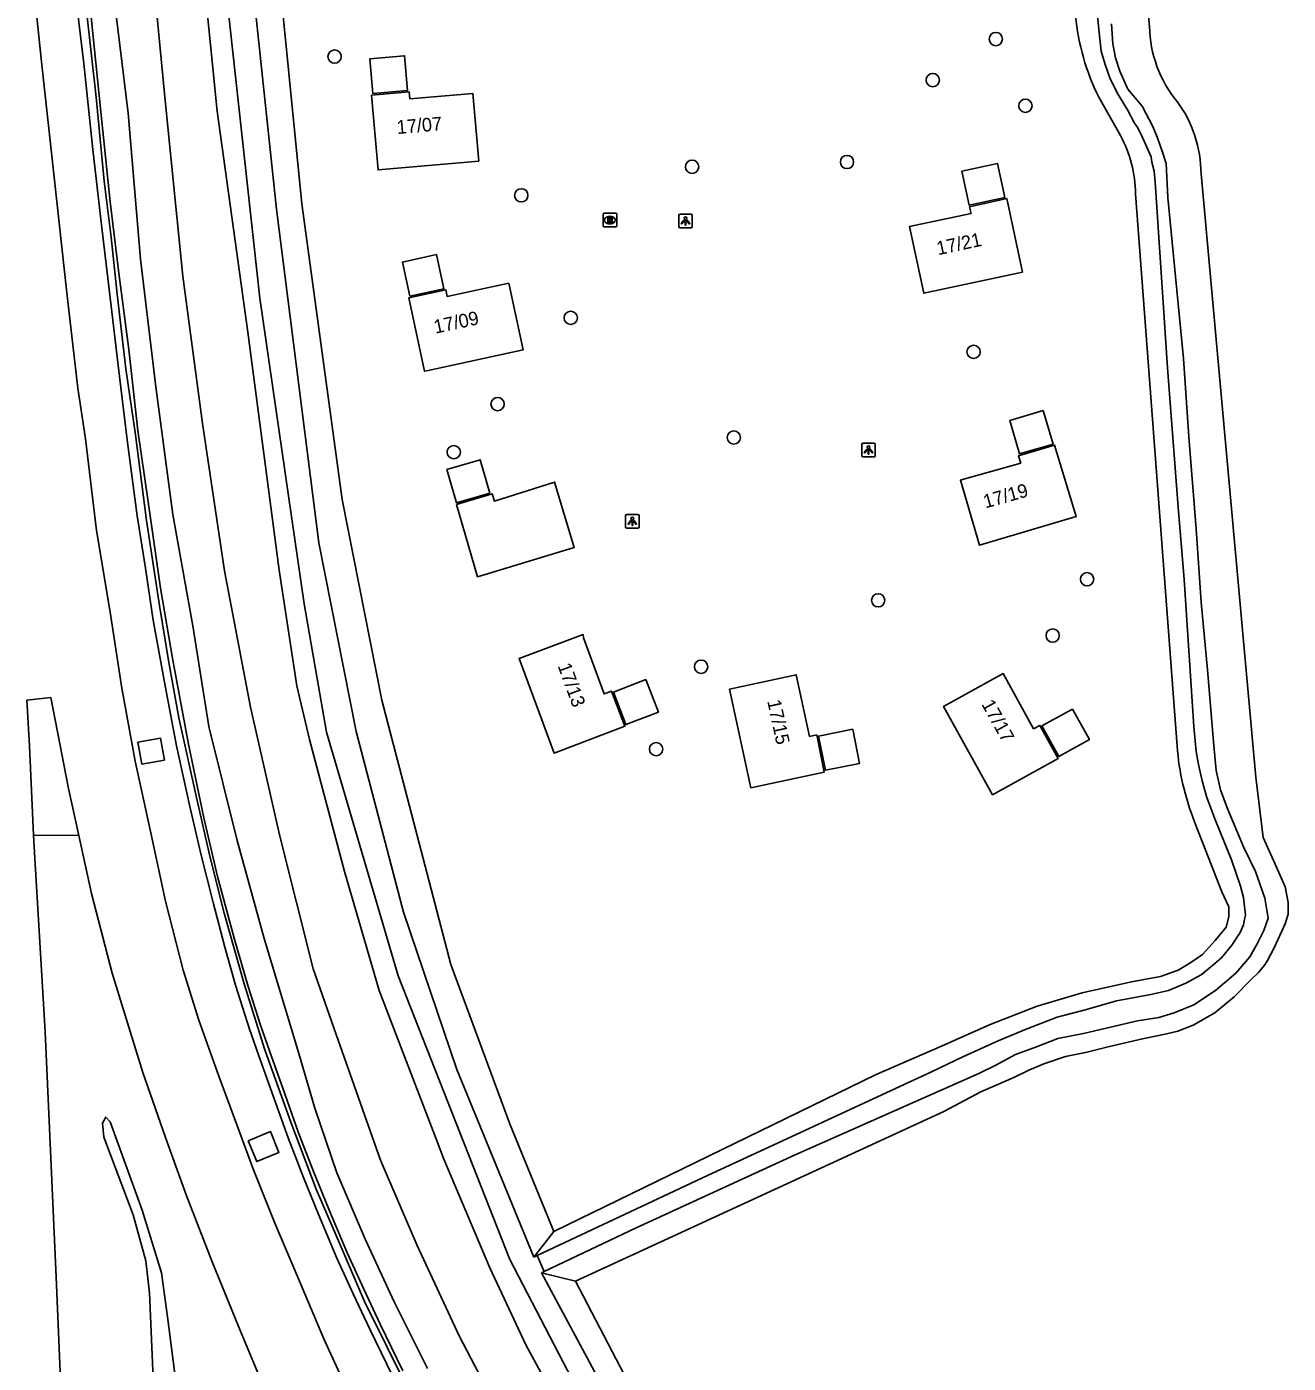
# Model space of a CAD drawing. Extents: x 157793 to 159380, y 380882 to 382313.
# Drawn here: x 157937.8 to 158030.6, y 381071.7 to 381170.1 of the extents above; entities that cross this region are included whole.
import ezdxf

# ---------------------------------------------------------------- set-up
doc = ezdxf.new("R2010")
doc.units = 0
for name, color, linetype in [('IMGEO_Berm_groen', 7, 'Continuous'), ('IMGEO_Berm_open', 7, 'Continuous'), ('IMGEO_Boom', 7, 'Continuous'), ('IMGEO_Geluidsscherm', 7, 'Continuous'), ('IMGEO_Grasland_overig', 7, 'Continuous'), ('IMGEO_Groenvoorziening', 7, 'Continuous'), ('IMGEO_Lichtpunt', 7, 'Continuous'), ('IMGEO_Muur', 7, 'Continuous'), ('IMGEO_Oever', 7, 'Continuous'), ('IMGEO_Pand', 7, 'Continuous'), ('IMGEO_Pand_nummerreeks', 7, 'Continuous'), ('IMGEO_Pand_vergunning_verleend', 7, 'Continuous'), ('IMGEO_Rijbaan_autoweg', 7, 'Continuous'), ('IMGEO_Rioolput', 7, 'Continuous'), ('IMGEO_Waterloop', 7, 'Continuous')]:
    doc.layers.add(name, color=color, linetype=linetype)

msp = doc.modelspace()

# ---------------------------------------------------------------- linework, layer by layer
at = {"layer": 'IMGEO_Berm_groen'}
for points in [[(157946.03, 381117.422), (157946.309, 381115.818), (157947.972, 381116.108), (157947.693, 381117.712), (157946.03, 381117.422)], [(157949.154, 381067.705), (157948.21, 381075.143), (157947.75, 381078.382), (157946.34, 381082.984), (157943.976, 381089.489), (157943.664, 381089.845), (157943.425, 381089.39), (157943.508, 381088.357), (157945.689, 381082.64), (157946.618, 381079.275), (157946.89, 381076.917), (157947.236, 381068.36)], [(157954.134, 381088.096), (157954.762, 381086.57), (157956.397, 381087.243), (157955.769, 381088.77), (157954.134, 381088.096)]]:
    msp.add_lwpolyline(points, dxfattribs=at)
at = {"layer": 'IMGEO_Berm_open'}
msp.add_lwpolyline([(157938.353, 381110.573), (157941.677, 381110.552)], dxfattribs=at)
at = {"layer": 'IMGEO_Boom'}
for centre in [(158009.132, 381169.157), (157960.493, 381167.864), (158004.492, 381166.14), (158011.308, 381164.25), (157998.185, 381160.109), (157986.791, 381159.761), (157974.228, 381157.657), (157977.862, 381148.644), (158007.497, 381146.143), (157972.484, 381142.3), (157989.858, 381139.842), (157969.256, 381138.76), (158015.843, 381129.408), (158000.478, 381127.86), (158013.314, 381125.266), (157987.454, 381122.977), (157984.142, 381116.908)]:
    msp.add_circle(centre, 0.489, dxfattribs=at)
at = {"layer": 'IMGEO_Geluidsscherm'}
msp.add_lwpolyline([(157942.251, 381171.224), (157942.964, 381164.872), (157943.555, 381158.711), (157944.056, 381154.583), (157944.505, 381150.378), (157945.148, 381144.887), (157945.845, 381140.036), (157946.668, 381133.736), (157947.611, 381127.489), (157948.287, 381123.427), (157949.046, 381119.227), (157950.385, 381113.14), (157951.307, 381109.043), (157952.366, 381104.849), (157953.831, 381099.642), (157955.371, 381094.796), (157957.264, 381089.477), (157959.132, 381084.541), (157960.921, 381080.39), (157962.699, 381076.283), (157964.365, 381072.915), (157966.426, 381068.742)], dxfattribs=at)
at = {"layer": 'IMGEO_Grasland_overig'}
for points in [[(157950.352, 381178.754), (157951.847, 381163.855), (157954.104, 381147.602), (157956.422, 381130.075), (157957.719, 381121.572), (157958.644, 381117.616), (157961.22, 381107.916), (157963.769, 381099.155), (157967.983, 381088.156), (157968.522, 381086.749), (157971.914, 381078.749), (157974.558, 381073.096), (157977.322, 381067.984), (157980.977, 381061.407), (157984.259, 381055.782), (157989.472, 381047.992), (157991.634, 381044.218), (157992.625, 381042.334), (157993.206, 381041.178), (157993.84, 381040.215), (157995.154, 381038.848), (157995.969, 381038.005)], [(157946.841, 381177.173), (157948.034, 381164.626), (157949.339, 381151.708), (157950.768, 381140.863), (157952.404, 381130.028), (157954.301, 381119.995), (157956.453, 381110.519), (157958.92, 381100.739), (157960.612, 381095.909), (157963.87, 381086.675), (157966.563, 381080.385), (157969.664, 381073.742), (157973.677, 381066.047)], [(157967.318, 381071.349), (157964.872, 381076.248), (157962.772, 381080.813), (157960.655, 381085.727), (157959.04, 381090.499), (157957.871, 381094.508), (157955.317, 381102.987), (157953.331, 381110.198), (157951.232, 381118.587), (157950.064, 381125.988), (157948.596, 381134.164), (157947.349, 381143.571), (157946.215, 381152.965), (157945.298, 381163.703), (157944.078, 381173.732)]]:
    msp.add_lwpolyline(points, dxfattribs=at)
at = {"layer": 'IMGEO_Groenvoorziening'}
for points in [[(157953.904, 381208.601), (157954.667, 381194.473), (157956.666, 381171.336), (157958.091, 381157.039), (157961.056, 381135.277), (157963.956, 381120.521), (157969.049, 381101.066), (157973.397, 381089.261), (157976.609, 381081.434)], [(158017.804, 381200.746), (158020.445, 381170.062)], [(158018.292, 381162.055), (158016.704, 381164.87)], [(158024.231, 381159.232), (158028.249, 381114.861), (158028.806, 381110.404), (158029.674, 381108.44), (158030.403, 381106.775), (158030.639, 381105.62), (158030.643, 381104.766), (158030.421, 381104.052), (158029.594, 381102.283), (158029.108, 381101.352), (158028.892, 381101.006), (158028.454, 381100.469), (158027.892, 381099.936), (158026.659, 381098.685), (158025.243, 381097.513), (158023.638, 381096.615), (158022.532, 381096.165), (158021.595, 381095.941), (158019.914, 381095.598), (158017.495, 381095.035), (158015.721, 381094.598), (158014.249, 381094.288), (158012.671, 381093.747), (158011.557, 381093.285), (158010.452, 381092.749), (158008.04, 381091.694), (158005.302, 381090.26), (157978.213, 381077.766)], [(158022.465, 381117.132), (158019.404, 381157.762)], [(157976.609, 381081.434), (158000.338, 381092.983), (158005.131, 381095.063), (158008.705, 381096.66), (158012.185, 381098.006), (158015.477, 381098.987), (158019.105, 381099.794), (158021.236, 381100.178), (158022.534, 381100.639), (158023.403, 381101.169), (158024.341, 381101.792), (158025.261, 381102.828), (158026.085, 381103.81), (158026.273, 381104.572), (158026.275, 381105.306), (158025.756, 381106.409), (158023.749, 381111.568)], [(157978.213, 381077.766), (157985.988, 381062.847), (157988.162, 381059.338)]]:
    msp.add_lwpolyline(points, dxfattribs=at)
for centre, radius, start, end in [((158032.528, 381172.642), 17.629, 185.77405, 206.15711), ((158029.237, 381170.181), 8.792, 180.7729, 219.65168), ((158015.08, 381159.168), 9.152, 0.39892, 36.17447), ((158010.58, 381157.767), 8.824, 359.96829, 29.0756), ((158041.64, 381118.627), 19.233, 184.45745, 201.53178)]:
    msp.add_arc(centre, radius, start, end, dxfattribs=at)
at = {"layer": 'IMGEO_Lichtpunt'}
for p, q in [((157985.809, 381156.175), (157985.809, 381155.368)), ((157985.809, 381156.175), (157985.809, 381155.368)), ((157986.711, 381156.27), (157985.903, 381156.27)), ((157986.711, 381156.27), (157985.903, 381156.27)), ((157986.805, 381155.368), (157986.805, 381156.175)), ((157986.805, 381155.368), (157986.805, 381156.175)), ((157985.903, 381155.274), (157986.711, 381155.274)), ((157985.903, 381155.274), (157986.711, 381155.274)), ((157999.271, 381139.327), (157999.271, 381138.52)), ((157999.271, 381139.327), (157999.271, 381138.52)), ((158000.173, 381139.422), (157999.365, 381139.422)), ((158000.173, 381139.422), (157999.365, 381139.422)), ((158000.267, 381138.52), (158000.267, 381139.327)), ((158000.267, 381138.52), (158000.267, 381139.327)), ((157999.365, 381138.426), (158000.173, 381138.426)), ((157999.365, 381138.426), (158000.173, 381138.426)), ((157981.896, 381134.074), (157981.896, 381133.267)), ((157981.896, 381134.074), (157981.896, 381133.267)), ((157982.798, 381134.169), (157981.99, 381134.169)), ((157982.798, 381134.169), (157981.99, 381134.169)), ((157982.892, 381133.267), (157982.892, 381134.074)), ((157982.892, 381133.267), (157982.892, 381134.074)), ((157981.99, 381133.173), (157982.798, 381133.173)), ((157981.99, 381133.173), (157982.798, 381133.173))]:
    msp.add_line(p, q, dxfattribs=at)
for points in [[(157986.183, 381155.839), (157986.222, 381155.811), (157986.034, 381155.549), (157985.996, 381155.576), (157986.183, 381155.839)], [(157986.285, 381155.791), (157986.332, 381155.791), (157986.332, 381155.469), (157986.285, 381155.469), (157986.285, 381155.791)], [(157986.395, 381155.811), (157986.433, 381155.838), (157986.62, 381155.576), (157986.581, 381155.548), (157986.395, 381155.811)], [(157999.645, 381138.991), (157999.684, 381138.963), (157999.496, 381138.701), (157999.458, 381138.728), (157999.645, 381138.991)], [(157999.747, 381138.943), (157999.794, 381138.943), (157999.794, 381138.621), (157999.747, 381138.621), (157999.747, 381138.943)], [(157999.857, 381138.963), (157999.895, 381138.99), (158000.082, 381138.728), (158000.043, 381138.7), (157999.857, 381138.963)], [(157982.27, 381133.738), (157982.309, 381133.71), (157982.121, 381133.448), (157982.083, 381133.475), (157982.27, 381133.738)], [(157982.482, 381133.71), (157982.52, 381133.737), (157982.707, 381133.475), (157982.668, 381133.447), (157982.482, 381133.71)], [(157982.372, 381133.69), (157982.419, 381133.69), (157982.419, 381133.368), (157982.372, 381133.368), (157982.372, 381133.69)]]:
    msp.add_lwpolyline(points, dxfattribs=at)
for centre in [(157986.308, 381155.973), (157999.77, 381139.125), (157982.395, 381133.872)]:
    msp.add_circle(centre, 0.0994, dxfattribs=at)
for centre, start, end in [((157985.903, 381156.175), 90, 180), ((157985.903, 381156.175), 90, 180), ((157985.903, 381155.368), 180, 270), ((157985.903, 381155.368), 180, 270), ((157986.711, 381156.175), 0, 90), ((157986.711, 381156.175), 0, 90), ((157986.711, 381155.368), 270, 0), ((157986.711, 381155.368), 270, 360), ((157999.365, 381139.327), 90, 180), ((157999.365, 381139.327), 90, 180), ((158000.173, 381139.327), 0, 90), ((158000.173, 381139.327), 0, 90), ((157999.365, 381138.52), 180, 270), ((157999.365, 381138.52), 180, 270), ((158000.173, 381138.52), 270, 0), ((158000.173, 381138.52), 270, 360), ((157981.99, 381134.074), 90, 180), ((157981.99, 381134.074), 90, 180), ((157982.798, 381134.074), 0, 90), ((157982.798, 381134.074), 0, 90), ((157981.99, 381133.267), 180, 270), ((157981.99, 381133.267), 180, 270), ((157982.798, 381133.267), 270, 0), ((157982.798, 381133.267), 270, 360)]:
    msp.add_arc(centre, 0.0946, start, end, dxfattribs=at)
at = {"layer": 'IMGEO_Muur'}
for points in [[(157964.763, 381070.791), (157963.075, 381074.245), (157961.865, 381076.827), (157960.652, 381079.462), (157959.337, 381082.618), (157958.196, 381085.396), (157957.077, 381088.307), (157956.033, 381091.265), (157954.902, 381094.429), (157954.239, 381096.317), (157953.208, 381099.555), (157952.414, 381102.353), (157951.559, 381105.636), (157950.663, 381109.199), (157949.835, 381112.691), (157948.867, 381117.143), (157948.032, 381121.564), (157947.149, 381126.396), (157946.596, 381130.229), (157945.977, 381134.078), (157945.254, 381139.463), (157944.66, 381144.327), (157944.052, 381149.501), (157943.367, 381155.264), (157942.72, 381161.037), (157942.046, 381167.363), (157941.317, 381173.452)], [(157942.585, 381170.761), (157943.299, 381163.808), (157943.979, 381157.181), (157944.591, 381152.13), (157945.353, 381146.315), (157946.027, 381140.364), (157946.745, 381135.271), (157947.692, 381128.751), (157948.587, 381123.469), (157949.753, 381117.27), (157950.863, 381111.848), (157951.88, 381107.54), (157953.115, 381103.016), (157954.143, 381099.459), (157955.041, 381096.599), (157955.703, 381094.713), (157956.834, 381091.549), (157957.874, 381088.601), (157958.986, 381085.71), (157960.122, 381082.943), (157961.431, 381079.804), (157962.636, 381077.185), (157963.842, 381074.612), (157965.522, 381071.172)]]:
    msp.add_lwpolyline(points, dxfattribs=at)
at = {"layer": 'IMGEO_Oever'}
for points in [[(157975.148, 381079.541), (157976.609, 381081.434)], [(157978.213, 381077.766), (157975.712, 381078.37)]]:
    msp.add_lwpolyline(points, dxfattribs=at)
at = {"layer": 'IMGEO_Pand'}
for points in [[(157965.864, 381165.369), (157963.309, 381165.145), (157963.085, 381167.7), (157965.641, 381167.924), (157965.864, 381165.369)], [(157971.097, 381160.17), (157963.695, 381159.522), (157963.214, 381165.021), (157965.989, 381165.264), (157966.034, 381164.753), (157970.661, 381165.157), (157971.097, 381160.17)], [(158006.631, 381159.434), (158009.248, 381160.002), (158009.784, 381157.493), (158007.175, 381156.927), (158006.631, 381159.434)], [(158007.31, 381156.325), (158007.199, 381156.817), (158009.94, 381157.412), (158011.096, 381152.014), (158003.83, 381150.459), (158002.782, 381155.356), (158007.31, 381156.325)], [(157968.539, 381150.788), (157966.032, 381150.244), (157965.488, 381152.751), (157967.995, 381153.294), (157968.539, 381150.788)], [(157973.312, 381151.206), (157974.376, 381146.294), (157967.371, 381144.775), (157967.115, 381144.72), (157965.946, 381150.115), (157968.667, 381150.705), (157968.772, 381150.222), (157973.312, 381151.206)], [(158012.62, 381141.82), (158013.343, 381139.359), (158010.885, 381138.643), (158010.164, 381141.099), (158012.62, 381141.82)], [(158010.979, 381137.949), (158010.808, 381138.501), (158013.46, 381139.28), (158015.052, 381134.022), (158007.924, 381131.927), (158006.524, 381136.689), (158006.671, 381136.738), (158010.979, 381137.949)], [(157971.914, 381135.752), (157969.471, 381135.04), (157968.75, 381137.481), (157971.191, 381138.201), (157971.914, 381135.752)], [(157978.797, 381125.102), (157980.311, 381120.97), (157980.857, 381121.178), (157981.848, 381118.598), (157976.644, 381116.621), (157974.059, 381123.587), (157978.772, 381125.336), (157978.797, 381125.102)], [(157983.398, 381122.031), (157984.318, 381119.636), (157981.923, 381118.717), (157981.004, 381121.111), (157983.398, 381122.031)], [(157995.431, 381117.842), (157995.954, 381117.956), (157996.508, 381115.227), (157991.111, 381114.066), (157989.549, 381121.33), (157994.454, 381122.385), (157995.431, 381117.842)], [(158011.915, 381118.409), (158012.372, 381118.662), (158013.72, 381116.225), (158008.892, 381113.551), (158005.292, 381120.05), (158009.663, 381122.472), (158011.915, 381118.409)], [(158014.773, 381119.859), (158016.014, 381117.614), (158013.77, 381116.373), (158012.528, 381118.617), (158014.773, 381119.859)], [(157998.618, 381118.371), (157999.109, 381115.866), (157996.595, 381115.356), (157996.085, 381117.869), (157998.618, 381118.371)]]:
    msp.add_lwpolyline(points, dxfattribs=at)
at = {"layer": 'IMGEO_Pand_vergunning_verleend'}
msp.add_lwpolyline([(157969.452, 381134.921), (157972.084, 381135.697), (157972.251, 381135.162), (157976.673, 381136.554), (157978.127, 381131.742), (157971.014, 381129.593), (157969.452, 381134.921)], dxfattribs=at)
at = {"layer": 'IMGEO_Rijbaan_autoweg'}
for points in [[(157961.157, 381070.357), (157959.701, 381073.533), (157957.84, 381077.935), (157956.107, 381082.027), (157954.538, 381085.951), (157953.274, 381089.345), (157951.979, 381092.844), (157950.509, 381096.979), (157949.363, 381100.642), (157948.055, 381105.717), (157946.925, 381110.978), (157945.834, 381116.025), (157944.85, 381121.388), (157943.975, 381126.999), (157942.988, 381133), (157942.162, 381139.742), (157941.596, 381143.471), (157940.803, 381150.496), (157939.873, 381158.989), (157938.934, 381167.481), (157938.07, 381175.761)], [(157941.677, 381110.552), (157940.926, 381114.005), (157939.613, 381120.704), (157937.848, 381120.505), (157938.04, 381117.163), (157938.353, 381110.573)], [(157938.353, 381110.573), (157938.413, 381109.3), (157939.215, 381096.105), (157940.023, 381078.051), (157940.618, 381063.515), (157941.195, 381047.312), (157941.6, 381033.915), (157942.157, 381020.637), (157943.116, 381002.941), (157943.879, 380987.756), (157944.647, 380971.403), (157945.538, 380956.668)], [(157955.581, 381069.266), (157953.442, 381074.391), (157951.493, 381079.191), (157949.565, 381084.115), (157948.044, 381088.339), (157946.385, 381093.118), (157944.122, 381100.437), (157942.607, 381106.281), (157941.677, 381110.552)]]:
    msp.add_lwpolyline(points, dxfattribs=at)
at = {"layer": 'IMGEO_Rioolput'}
for p, q in [((157980.318, 381156.338), (157981.17, 381156.338)), ((157980.243, 381155.412), (157980.243, 381156.264)), ((157980.754, 381155.558), (157980.729, 381155.558)), ((157980.731, 381156.118), (157980.756, 381156.118)), ((157981.244, 381156.264), (157981.244, 381155.412)), ((157981.17, 381155.338), (157980.318, 381155.338))]:
    msp.add_line(p, q, dxfattribs=at)
for points in [[(157980.318, 381156.338), (157981.17, 381156.338)], [(157980.243, 381155.412), (157980.243, 381156.264)], [(157980.832, 381156.036), (157980.58, 381156.038), (157980.58, 381155.638)], [(157980.58, 381155.638), (157980.704, 381155.638), (157980.704, 381155.8), (157980.715, 381155.8)], [(157980.758, 381155.957), (157980.704, 381155.957), (157980.704, 381155.876)], [(157980.704, 381155.876), (157980.756, 381155.876)], [(157980.762, 381155.771), (157980.833, 381155.638), (157980.973, 381155.638), (157980.908, 381155.764)], [(157981.244, 381156.264), (157981.244, 381155.412)], [(157981.17, 381155.338), (157980.318, 381155.338)]]:
    msp.add_lwpolyline(points, dxfattribs=at)
for centre, radius, start, end in [((157980.32, 381156.262), 0.0765, 91.55205, 178.44795), ((157980.32, 381156.262), 0.0765, 91.55205, 178.44795), ((157981.168, 381156.262), 0.0765, 1.55205, 88.44795), ((157981.168, 381156.262), 0.0765, 1.55205, 88.44795), ((157980.32, 381155.414), 0.0765, 181.55205, 268.44795), ((157980.32, 381155.414), 0.0765, 181.55205, 268.44795), ((157980.714, 381155.747), 0.0533, 26.02933, 88.69889), ((157980.74, 381156.065), 0.19, 274.7715, 282.96867), ((157980.764, 381155.861), 0.0964, 77.00612, 93.18647), ((157980.778, 381155.918), 0.0378, 276.66336, 79.67722), ((157980.831, 381155.926), 0.109, 350.36119, 89.41601), ((157980.829, 381155.926), 0.112, 277.58423, 350.98172), ((157980.813, 381155.711), 0.108, 29.51342, 73.79051), ((157981.168, 381155.414), 0.0765, 271.55205, 358.44795), ((157981.168, 381155.414), 0.0765, 271.55205, 358.44795)]:
    msp.add_arc(centre, radius, start, end, dxfattribs=at)
for centre, major_axis, ratio, start_param, end_param in [((157980.73, 381155.838), (-0.387, 0.002), 0.722429, 4.712389, 7.853982), ((157980.755, 381155.838), (-0.39, 0.002), 0.717154, 1.570796, 4.712389)]:
    msp.add_ellipse(centre, major_axis=major_axis, ratio=ratio, start_param=start_param, end_param=end_param, dxfattribs=at)
at = {"layer": 'IMGEO_Waterloop'}
for points in [[(157994.736, 381043.033), (157990.832, 381048.744), (157980.887, 381064.91), (157973.374, 381079.353), (157965.169, 381100.228), (157959.887, 381118.158), (157958.251, 381127.609), (157955.004, 381150.088), (157952.562, 381172.238), (157950.691, 381196.021), (157949.616, 381210.978), (157947.442, 381244.345), (157945.886, 381265.31), (157944.557, 381281.595)], [(157975.148, 381079.541), (157969.49, 381093.331), (157965.564, 381104.907), (157962.076, 381118.203), (157959.332, 381132.084), (157956.217, 381156.646), (157953.818, 381179.321), (157951.776, 381209.989)], [(157975.402, 381079.661), (157987.916, 381085.554), (157993.433, 381088.104), (158004.407, 381093.16), (158006.716, 381094.266), (158009.315, 381095.446), (158011.367, 381096.313), (158013.644, 381097.193), (158015.795, 381097.763), (158018.016, 381098.394), (158020.528, 381098.858), (158021.831, 381099.148), (158023.11, 381099.682), (158024.236, 381100.305), (158024.918, 381100.863), (158025.723, 381101.562), (158026.501, 381102.478), (158027.109, 381103.412), (158027.346, 381103.979), (158027.429, 381104.402), (158027.496, 381104.708), (158027.359, 381105.986), (158027.127, 381106.831), (158026.457, 381108.777), (158025.282, 381111.66), (158024.643, 381113.345), (158024.321, 381114.573), (158024.037, 381115.775), (158023.871, 381116.733), (158023.689, 381118.57), (158022.986, 381129.399), (158022.539, 381134.705), (158021.765, 381144.973), (158020.844, 381158.618), (158020.787, 381159.431), (158020.611, 381160.101), (158020.547, 381160.494), (158019.818, 381162.127), (158019.522, 381162.709), (158019.342, 381162.956), (158018.808, 381163.947), (158018.121, 381165.072), (158017.543, 381166.235), (158017.153, 381167.365), (158016.872, 381168.263), (158016.705, 381169.852), (158016.044, 381176.875)], [(158017.65, 381170.266), (158017.734, 381168.814), (158017.935, 381167.763), (158018.242, 381166.799), (158018.832, 381165.468), (158019.891, 381164.206), (158020.688, 381162.718), (158021.054, 381161.824), (158021.384, 381160.844), (158021.653, 381160.006), (158021.781, 381157.505), (158022.349, 381151.689), (158022.926, 381145.664), (158023.318, 381139.893), (158023.869, 381133.121), (158024.24, 381127.735), (158024.691, 381122.754), (158025.173, 381117.167), (158025.339, 381115.351), (158025.659, 381113.919), (158026.153, 381112.588), (158027.342, 381109.73), (158028.232, 381107.905), (158028.922, 381105.953), (158029.16, 381104.48), (158028.858, 381103.564), (158028.363, 381102.587), (158027.805, 381101.62), (158026.789, 381100.44), (158025.3, 381099.15), (158023.707, 381098.11), (158022.254, 381097.512), (158021.131, 381097.175), (158019.544, 381096.919), (158015.588, 381095.993), (158013.693, 381095.632), (158012.115, 381095.007), (158010.585, 381094.45), (158009.136, 381093.671), (158007.873, 381093.055), (158003.624, 381091.17), (157994.367, 381087.051), (157982.673, 381081.688), (157975.919, 381078.469)], [(157975.402, 381079.661), (157975.148, 381079.541)], [(157975.919, 381078.469), (157975.402, 381079.661)], [(157975.712, 381078.37), (157975.919, 381078.469)], [(157975.712, 381078.37), (157982.974, 381064.879), (157988.769, 381055.21), (157994.622, 381045.657), (157995.76, 381043.824)]]:
    msp.add_lwpolyline(points, dxfattribs=at)

# ---------------------------------------------------------------- texts
at = {"layer": 'IMGEO_Pand_nummerreeks'}
for s, rotation, p in [('17/07', 4.99046, (157965.104, 381162.162)), ('17/21', 12.07795, (158004.887, 381153.25)), ('17/09', 12.22692, (157967.908, 381147.476)), ('17/19', 15.69904, (158008.37, 381134.618)), ('17/13', 290.12207, (157976.887, 381123.048)), ('17/15', 282.13504, (157992.314, 381120.445)), ('17/17', 298.99718, (158008.05, 381120.226))]:
    msp.add_text(s, height=1, rotation=rotation, dxfattribs=at).set_placement(p)

doc.saveas('drawing.dxf')
